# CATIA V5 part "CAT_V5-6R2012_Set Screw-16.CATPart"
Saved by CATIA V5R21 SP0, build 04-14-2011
Part number: Set Screw-16
Bounding box of the stored display mesh (mm): x -5.916 to 5.916, y -5.998 to 5.998, z -1.5 to 20.171
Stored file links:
  D:\CATIA V5R21 E-RESOURCES\CATIA-V5R21\catia-v5r21-prt\c16-catia-v5r20-prt\c16-catia-v5r21-tut01\CAT_V5R21_Set Screw-16.CATPart
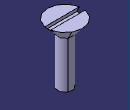
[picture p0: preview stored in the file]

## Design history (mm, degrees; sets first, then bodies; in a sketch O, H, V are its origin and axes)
Body1 (main body)
  Sketch1 on yz-plane, origin (0, 0, 0), H (0, 1, 0), V (0, 0, 1)
    point P1 (0, -1.5)
    line L1 (0, -1.5) -> (2.5, 0)
    point P2 (2.5, 0)
    line L2 (2.5, 0) -> (2.5, 16)
    line L3 (2.5, 16) -> (6, 20.1711)
    point P4 (6, 20.1711)
    line L4 (6, 20.1711) -> (0, 20.1711)
    point P5 (0, 20.1711)
    line L5 (0, 20.1711) -> (0, -1.5)
    length L2 = 16
    distance L2 L5 = 2.5
    distance H P1 = 1.5
    distance P4 L5 = 6
    angle L3 L5 = 40
    coincidence: P1 V, P2 H, P5 V
    vertical: L2 V, L5 V
    horizontal: L4 H
  Shaft1: profile Sketch1, axis edge of Sketch1, angle 360
  Sketch2 on yz-plane, origin (0, 0, 0), H (0, 1, 0), V (0, 0, 1)
    line L1 (-1, 20.1711) -> (1, 20.1711)
    line L2 (1, 20.1711) -> (1, 19.1711)
    line L3 (1, 19.1711) -> (-1, 19.1711)
    line L4 (-1, 19.1711) -> (-1, 20.1711)
    reference projected line E1 (-6, 20.1711) -> (6, 20.1711) from edge of Shaft1
    distance V L2 = 1
    length L1 = 2
    length L2 = 1
    horizontal: L1 H, L3 H
    vertical: L2 V, L4 V
    coincidence: L1 E1
  Pocket1: profile Sketch2, direction (-1, 0, 0), length 16, mirrored extent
